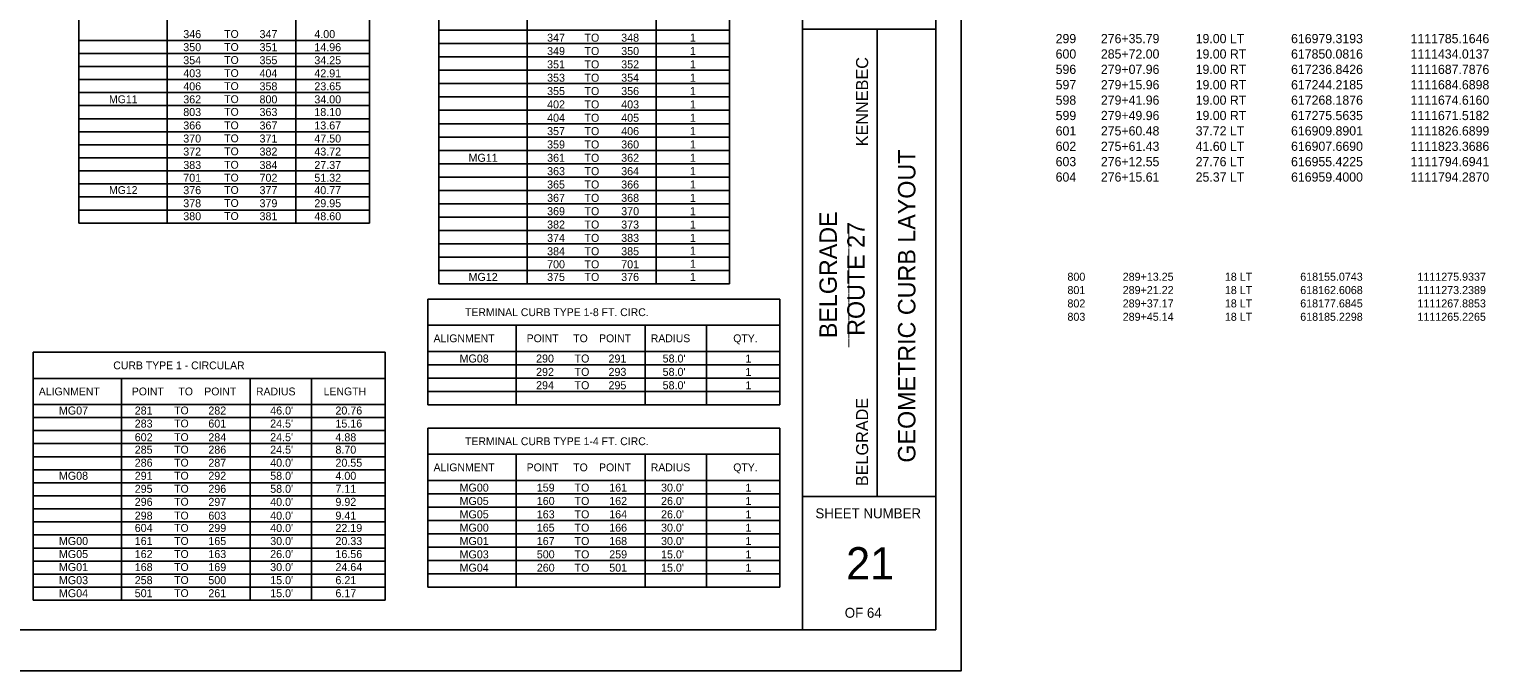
# Model space of a CAD drawing. Extents: x -415 to 632, y -278 to 272.
# Drawn here: x 85 to 632, y -278 to -37 of the extents above; entities that cross this region are included whole.
import ezdxf

# ---------------------------------------------------------------- set-up
doc = ezdxf.new("R2010")
doc.units = 0
for name, color, linetype in [('ANNOTATION', 7, 'Continuous'), ('BORDER', 7, 'Continuous'), ('BRIDGE_TITLE', 7, 'Continuous'), ('H_V CONTROLS', 7, 'Continuous'), ('HIGHWAY_TITLE', 7, 'Continuous'), ('PLOT BOUNDARY', 7, 'Continuous')]:
    doc.layers.add(name, color=color, linetype=linetype)

msp = doc.modelspace()

# ---------------------------------------------------------------- linework, layer by layer
at = {"layer": 'BORDER'}
for p, q in [((375, -262.5), (375, 262.5)), ((425, -262.49), (425, 262.51)), ((375, -37.49), (425, -37.49)), ((402.96, -212.49), (402.96, -37.49)), ((375, -212.49), (425, -212.49)), ((-375, -262.5), (425, -262.5))]:
    msp.add_line(p, q, dxfattribs=at)
at = {"layer": 'H_V CONTROLS'}
for p, q in [((103.65, 246.69), (103.65, -110.1)), ((212.69, 246.69), (212.69, -110.1)), ((238.63, 246.69), (238.63, -132.86)), ((347.68, 246.69), (347.68, -132.86)), ((136.79, 236.92), (136.79, -110.1)), ((185.09, 236.92), (185.09, -110.1)), ((271.78, 236.92), (271.78, -132.86)), ((320.08, 236.92), (320.08, -132.86)), ((238.63, -37.86), (347.68, -37.86)), ((103.65, -41.67), (212.69, -41.67)), ((238.63, -42.86), (347.68, -42.86)), ((103.65, -46.56), (212.69, -46.56)), ((238.63, -47.86), (347.68, -47.86)), ((103.65, -51.45), (212.69, -51.45)), ((238.63, -52.86), (347.68, -52.86)), ((103.65, -56.33), (212.69, -56.33)), ((238.63, -57.86), (347.68, -57.86)), ((103.65, -61.22), (212.69, -61.22)), ((238.63, -62.86), (347.68, -62.86)), ((238.63, -62.86), (347.68, -62.86)), ((103.65, -66.11), (212.69, -66.11)), ((103.65, -71), (212.69, -71)), ((238.63, -67.86), (347.68, -67.86)), ((103.65, -75.88), (212.69, -75.88)), ((238.63, -72.86), (347.68, -72.86)), ((103.65, -80.77), (212.69, -80.77)), ((238.63, -77.86), (347.68, -77.86)), ((103.65, -85.66), (212.69, -85.66)), ((238.63, -82.86), (347.68, -82.86)), ((103.65, -90.55), (212.69, -90.55)), ((238.63, -87.86), (347.68, -87.86)), ((238.63, -92.86), (347.68, -92.86)), ((103.65, -95.43), (212.69, -95.43)), ((238.63, -97.86), (347.68, -97.86)), ((103.65, -100.32), (212.69, -100.32)), ((238.63, -102.86), (347.68, -102.86)), ((103.65, -105.21), (212.69, -105.21)), ((238.63, -107.86), (347.68, -107.86)), ((103.65, -110.1), (212.69, -110.1)), ((103.65, -110.1), (212.69, -110.1)), ((238.63, -112.86), (347.68, -112.86)), ((238.63, -117.86), (347.68, -117.86)), ((238.63, -122.86), (347.68, -122.86)), ((238.63, -122.86), (347.68, -122.86)), ((238.63, -127.86), (347.68, -127.86)), ((238.63, -132.86), (347.68, -132.86)), ((238.63, -132.86), (347.68, -132.86)), ((234.51, -138.59), (366.55, -138.59)), ((234.51, -138.59), (234.51, -178.14)), ((234.51, -138.59), (234.51, -178.14)), ((366.55, -138.59), (366.55, -178.14)), ((234.51, -148.36), (366.55, -148.36)), ((267.65, -148.36), (267.65, -178.14)), ((267.65, -148.36), (267.65, -178.14)), ((315.95, -148.36), (315.95, -178.14)), ((315.95, -148.36), (315.95, -178.14)), ((338.95, -148.36), (338.95, -178.14)), ((86.5, -158.51), (218.54, -158.51)), ((86.5, -158.51), (86.5, -251.37)), ((218.54, -158.51), (218.54, -251.37)), ((234.51, -158.14), (366.55, -158.14)), ((234.51, -158.14), (343.55, -158.14)), ((234.51, -163.14), (366.55, -163.14)), ((86.5, -168.28), (218.54, -168.28)), ((119.64, -168.28), (119.64, -251.37)), ((167.94, -168.28), (167.94, -251.37)), ((190.94, -168.28), (190.94, -251.37)), ((234.51, -168.14), (366.55, -168.14)), ((234.51, -173.14), (366.55, -173.14)), ((86.5, -178.06), (218.54, -178.06)), ((234.51, -178.14), (366.55, -178.14)), ((234.51, -178.14), (366.55, -178.14)), ((86.5, -182.94), (218.54, -182.94)), ((86.5, -187.83), (218.54, -187.83)), ((234.51, -186.93), (366.55, -186.93)), ((234.51, -186.93), (234.51, -246.48)), ((234.51, -186.93), (234.51, -246.48)), ((366.55, -186.93), (366.55, -246.48)), ((86.5, -192.72), (218.54, -192.72)), ((234.51, -196.71), (366.55, -196.71)), ((267.65, -196.71), (267.65, -246.48)), ((267.65, -196.71), (267.65, -246.48)), ((315.95, -196.71), (315.95, -246.48)), ((315.95, -196.71), (315.95, -246.48)), ((338.95, -196.71), (338.95, -246.48)), ((86.5, -197.61), (218.54, -197.61)), ((86.5, -202.49), (218.54, -202.49)), ((86.5, -207.38), (218.54, -207.38)), ((234.51, -206.48), (366.55, -206.48)), ((234.51, -206.48), (343.55, -206.48)), ((86.5, -212.27), (218.54, -212.27)), ((234.51, -211.48), (366.55, -211.48)), ((86.5, -217.16), (218.54, -217.16)), ((234.51, -216.48), (366.55, -216.48)), ((86.5, -222.04), (218.54, -222.04)), ((234.51, -221.48), (366.55, -221.48)), ((86.5, -226.93), (218.54, -226.93)), ((234.51, -226.48), (366.55, -226.48)), ((86.5, -231.82), (218.54, -231.82)), ((234.51, -231.48), (366.55, -231.48)), ((86.5, -236.71), (218.54, -236.71)), ((234.51, -236.48), (366.55, -236.48)), ((86.5, -241.59), (218.54, -241.59)), ((234.51, -241.48), (366.55, -241.48)), ((86.5, -246.48), (218.54, -246.48)), ((86.5, -251.37), (218.54, -251.37)), ((234.51, -246.48), (366.55, -246.48)), ((234.51, -246.48), (366.55, -246.48))]:
    msp.add_line(p, q, dxfattribs=at)
at = {"layer": 'PLOT BOUNDARY'}
msp.add_lwpolyline([(-415.47, -277.8), (434.53, -277.8), (434.53, 272.2), (-415.47, 272.2)], close=True, dxfattribs=at)

# ---------------------------------------------------------------- texts
at = {"layer": 'ANNOTATION'}
for s, height, p in [('346', 3, (142.83, -40.81)), ('347', 3, (171.42, -40.81)), ('4.00', 3, (191.97, -40.81)), ('350', 3, (142.83, -45.7)), ('351', 3, (171.42, -45.7)), ('14.96', 3, (191.97, -45.7)), ('347', 3, (279.24, -42.14)), ('TO', 3, (293.24, -42.14)), ('348', 3, (307.02, -42.14)), ('1', 3, (332.76, -42.14)), ('299', 3.45, (469.9, -42.71)), ('276+35.79', 3.45, (486.86, -42.71)), ('19.00 LT', 3.45, (522.4, -42.71)), ('616979.3193', 3.45, (558.16, -42.71)), ('1111785.1646', 3.45, (602.97, -42.71)), ('354', 3, (142.83, -50.59)), ('355', 3, (171.42, -50.59)), ('34.25', 3, (191.97, -50.59)), ('349', 3, (279.24, -47.14)), ('351', 3, (279.24, -52.14)), ('TO', 3, (293.24, -47.14)), ('TO', 3, (293.24, -52.14)), ('350', 3, (307.02, -47.14)), ('352', 3, (307.02, -52.14)), ('1', 3, (332.76, -47.14)), ('1', 3, (332.76, -52.14)), ('600', 3.45, (469.9, -48.47)), ('285+72.00', 3.45, (486.86, -48.47)), ('19.00 RT', 3.45, (522.4, -48.47)), ('617850.0816', 3.45, (558.16, -48.47)), ('1111434.0137', 3.45, (602.97, -48.47)), ('403', 3, (142.83, -55.48)), ('404', 3, (171.42, -55.48)), ('42.91', 3, (191.97, -55.48)), ('353', 3, (279.24, -57.14)), ('TO', 3, (293.24, -57.14)), ('354', 3, (307.02, -57.14)), ('1', 3, (332.76, -57.14)), ('596', 3.45, (469.9, -54.23)), ('279+07.96', 3.45, (486.86, -54.23)), ('19.00 RT', 3.45, (522.4, -54.23)), ('617236.8426', 3.45, (558.16, -54.23)), ('1111687.7876', 3.45, (602.97, -54.23)), ('406', 3, (142.83, -60.36)), ('358', 3, (171.42, -60.36)), ('23.65', 3, (191.97, -60.36)), ('355', 3, (279.24, -62.14)), ('TO', 3, (293.24, -62.14)), ('356', 3, (307.02, -62.14)), ('1', 3, (332.76, -62.14)), ('597', 3.45, (469.9, -60)), ('279+15.96', 3.45, (486.86, -60)), ('19.00 RT', 3.45, (522.4, -60)), ('617244.2185', 3.45, (558.16, -60)), ('1111684.6898', 3.45, (602.97, -60)), ('362', 3, (142.83, -65.25)), ('800', 3, (171.42, -65.25)), ('34.00', 3, (191.97, -65.25)), ('402', 3, (279.24, -67.14)), ('TO', 3, (293.24, -67.14)), ('403', 3, (307.02, -67.14)), ('1', 3, (332.76, -67.14)), ('598', 3.45, (469.9, -65.76)), ('279+41.96', 3.45, (486.86, -65.76)), ('19.00 RT', 3.45, (522.4, -65.76)), ('617268.1876', 3.45, (558.16, -65.76)), ('1111674.6160', 3.45, (602.97, -65.76)), ('803', 3, (142.83, -70)), ('363', 3, (171.42, -70)), ('18.10', 3, (191.97, -70)), ('404', 3, (279.24, -72.14)), ('TO', 3, (293.24, -72.14)), ('405', 3, (307.02, -72.14)), ('1', 3, (332.76, -72.14)), ('599', 3.45, (469.9, -71.52)), ('279+49.96', 3.45, (486.86, -71.52)), ('19.00 RT', 3.45, (522.4, -71.52)), ('617275.5635', 3.45, (558.16, -71.52)), ('1111671.5182', 3.45, (602.97, -71.52)), ('366', 3, (142.83, -75.03)), ('367', 3, (171.42, -75.03)), ('13.67', 3, (191.97, -75.03)), ('357', 3, (279.24, -77.14)), ('TO', 3, (293.24, -77.14)), ('406', 3, (307.02, -77.14)), ('1', 3, (332.76, -77.14)), ('601', 3.45, (469.9, -77.28)), ('275+60.48', 3.45, (486.86, -77.28)), ('37.72 LT', 3.45, (522.4, -77.28)), ('616909.8901', 3.45, (558.16, -77.28)), ('1111826.6899', 3.45, (602.97, -77.28)), ('370', 3, (142.83, -79.92)), ('372', 3, (142.83, -84.8)), ('371', 3, (171.42, -79.92)), ('382', 3, (171.42, -84.8)), ('47.50', 3, (191.97, -79.92)), ('43.72', 3, (191.97, -84.8)), ('359', 3, (279.24, -82.14)), ('TO', 3, (293.24, -82.14)), ('360', 3, (307.02, -82.14)), ('1', 3, (332.76, -82.14)), ('602', 3.45, (469.9, -83.04)), ('275+61.43', 3.45, (486.86, -83.04)), ('41.60 LT', 3.45, (522.4, -83.04)), ('616907.6690', 3.45, (558.16, -83.04)), ('1111823.3686', 3.45, (602.97, -83.04)), ('383', 3, (142.83, -89.83)), ('384', 3, (171.42, -89.83)), ('27.37', 3, (191.97, -89.83)), ('MG11', 3, (249.79, -87.14)), ('361', 3, (279.24, -87.14)), ('TO', 3, (293.24, -87.14)), ('362', 3, (307.02, -87.14)), ('1', 3, (332.76, -87.14)), ('603', 3.45, (469.9, -88.8)), ('276+12.55', 3.45, (486.86, -88.8)), ('27.76 LT', 3.45, (522.4, -88.8)), ('616955.4225', 3.45, (558.16, -88.8)), ('1111794.6941', 3.45, (602.97, -88.8)), ('701', 3, (142.83, -94.62)), ('702', 3, (171.42, -94.62)), ('51.32', 3, (191.97, -94.62)), ('363', 3, (279.24, -92.14)), ('TO', 3, (293.24, -92.14)), ('364', 3, (307.02, -92.14)), ('1', 3, (332.76, -92.14)), ('604', 3.45, (469.9, -94.57)), ('276+15.61', 3.45, (486.86, -94.57)), ('25.37 LT', 3.45, (522.4, -94.57)), ('616959.4000', 3.45, (558.16, -94.57)), ('1111794.2870', 3.45, (602.97, -94.57)), ('376', 3, (142.83, -99.26)), ('377', 3, (171.42, -99.26)), ('40.77', 3, (191.97, -99.26)), ('365', 3, (279.24, -97.14)), ('TO', 3, (293.24, -97.14)), ('366', 3, (307.02, -97.14)), ('1', 3, (332.76, -97.14)), ('378', 3, (142.83, -104.15)), ('379', 3, (171.42, -104.15)), ('29.95', 3, (191.97, -104.15)), ('367', 3, (279.24, -102.14)), ('TO', 3, (293.24, -102.14)), ('368', 3, (307.02, -102.14)), ('1', 3, (332.76, -102.14)), ('380', 3, (142.83, -109.04)), ('381', 3, (171.42, -109.04)), ('48.60', 3, (191.97, -109.04)), ('369', 3, (279.24, -107.14)), ('382', 3, (279.24, -112.14)), ('TO', 3, (293.24, -107.14)), ('TO', 3, (293.24, -112.14)), ('370', 3, (307.02, -107.14)), ('373', 3, (307.02, -112.14)), ('1', 3, (332.76, -107.14)), ('1', 3, (332.76, -112.14)), ('374', 3, (279.24, -117.14)), ('TO', 3, (293.24, -117.14)), ('383', 3, (307.02, -117.14)), ('1', 3, (332.76, -117.14)), ('384', 3, (279.24, -122.14)), ('TO', 3, (293.24, -122.14)), ('385', 3, (307.02, -122.14)), ('1', 3, (332.76, -121.95)), ('700', 3, (279.24, -127.03)), ('TO', 3, (293.24, -127.03)), ('701', 3, (307.02, -127.03)), ('1', 3, (332.76, -126.85)), ('MG12', 3, (249.79, -131.77)), ('375', 3, (279.24, -131.77)), ('TO', 3, (293.24, -131.77)), ('376', 3, (307.02, -131.77)), ('1', 3, (332.76, -131.77)), ('800', 3, (474.32, -131.69)), ('289+13.25', 3, (495.04, -131.69)), ('18 LT', 3, (533.34, -131.69)), ('618155.0743', 3, (561.6, -131.69)), ('1111275.9337', 3, (605.55, -131.69)), ('801', 3, (474.32, -136.69)), ('289+21.22', 3, (495.04, -136.69)), ('18 LT', 3, (533.34, -136.69)), ('618162.6068', 3, (561.6, -136.69)), ('1111273.2389', 3, (605.55, -136.69)), ('802', 3, (474.32, -141.69)), ('289+37.17', 3, (495.04, -141.69)), ('18 LT', 3, (533.34, -141.69)), ('618177.6845', 3, (561.6, -141.69)), ('1111267.8853', 3, (605.55, -141.69)), ('803', 3, (474.32, -146.69)), ('289+45.14', 3, (495.04, -146.69)), ('18 LT', 3, (533.34, -146.69)), ('618185.2298', 3, (561.6, -146.69)), ('1111265.2265', 3, (605.55, -146.69)), ('MG08', 3, (246.42, -162.33)), ('290', 3, (275.11, -162.33)), ('TO', 3, (289.52, -162.33)), ('291', 3, (302.26, -162.33)), ("58.0'", 3, (322.55, -162.33)), ('1', 3, (353.6, -162.33)), ('292', 3, (275.11, -167.33)), ('294', 3, (275.11, -172.33)), ('TO', 3, (289.52, -167.33)), ('TO', 3, (289.52, -172.33)), ('293', 3, (302.26, -167.33)), ('295', 3, (302.26, -172.33)), ("58.0'", 3, (322.55, -167.33)), ("58.0'", 3, (322.55, -172.33)), ('1', 3, (353.6, -167.33)), ('1', 3, (353.6, -172.33)), ('MG07', 3, (96.21, -181.81)), ('281', 3, (124.63, -181.81)), ('282', 3, (152.23, -181.81)), ("46.0'", 3, (175.42, -181.81)), ('20.76', 3, (199.88, -181.81)), ('283', 3, (124.63, -186.69)), ('601', 3, (152.23, -186.69)), ("24.5'", 3, (175.42, -186.69)), ('15.16', 3, (199.88, -186.69)), ('602', 3, (124.63, -191.81)), ('284', 3, (152.23, -191.81)), ("24.5'", 3, (175.42, -191.81)), ('4.88', 3, (199.88, -191.81)), ('285', 3, (124.63, -196.47)), ('286', 3, (152.23, -196.47)), ("24.5'", 3, (175.42, -196.47)), ('8.70', 3, (199.88, -196.47)), ('286', 3, (124.63, -201.36)), ('287', 3, (152.23, -201.36)), ("40.0'", 3, (175.42, -201.36)), ('20.55', 3, (199.88, -201.36)), ('MG08', 3, (96.21, -206.25)), ('291', 3, (124.63, -206.25)), ('292', 3, (152.23, -206.25)), ("58.0'", 3, (175.42, -206.25)), ('4.00', 3, (199.88, -206.25)), ('MG00', 3, (246.42, -210.68)), ('159', 3, (275.37, -210.68)), ('TO', 3, (289.52, -210.68)), ('161', 3, (302.53, -210.68)), ("30.0'", 3, (321.96, -210.68)), ('1', 3, (353.6, -210.68)), ('295', 3, (124.63, -211.13)), ('296', 3, (124.63, -216.02)), ('296', 3, (152.23, -211.13)), ('297', 3, (152.23, -216.02)), ("40.0'", 3, (175.42, -216.02)), ("58.0'", 3, (175.42, -211.13)), ('9.92', 3, (199.88, -216.02)), ('7.11', 3, (199.88, -211.13)), ('MG05', 3, (246.42, -215.68)), ('160', 3, (275.37, -215.68)), ('TO', 3, (289.52, -215.68)), ('162', 3, (302.53, -215.68)), ("26.0'", 3, (321.96, -215.68)), ('1', 3, (353.6, -215.68)), ('298', 3, (124.63, -221.18)), ('603', 3, (152.23, -221.18)), ("40.0'", 3, (175.42, -221.18)), ('9.41', 3, (199.88, -221.18)), ('MG05', 3, (246.42, -220.68)), ('163', 3, (275.37, -220.68)), ('TO', 3, (289.52, -220.68)), ('164', 3, (302.53, -220.68)), ("26.0'", 3, (321.96, -220.68)), ('1', 3, (353.6, -220.68)), ('604', 3, (124.63, -225.8)), ('299', 3, (152.23, -225.8)), ("40.0'", 3, (175.42, -225.8)), ('22.19', 3, (199.88, -225.8)), ('MG00', 3, (246.42, -225.68)), ('165', 3, (275.37, -225.68)), ('TO ', 3, (289.52, -225.68)), ('166', 3, (302.53, -225.68)), ("30.0'", 3, (321.96, -225.68)), ('1', 3, (353.6, -225.68)), ('MG00', 3, (96.21, -230.69)), ('161', 3, (124.63, -230.69)), ('165', 3, (152.23, -230.69)), ("30.0'", 3, (175.42, -230.69)), ('20.33', 3, (199.88, -230.69)), ('MG01', 3, (246.42, -230.68)), ('167', 3, (275.37, -230.68)), ('TO', 3, (289.52, -230.68)), ('168', 3, (302.53, -230.68)), ("30.0'", 3, (321.96, -230.68)), ('1', 3, (353.6, -230.68)), ('MG05', 3, (96.21, -235.57)), ('162', 3, (124.63, -235.57)), ('163', 3, (152.23, -235.57)), ("26.0'", 3, (175.42, -235.57)), ('16.56', 3, (199.88, -235.57)), ('MG03', 3, (246.42, -235.68)), ('500', 3, (275.37, -235.68)), ('TO', 3, (289.52, -235.68)), ('259', 3, (302.53, -235.68)), ("15.0'", 3, (321.96, -235.68)), ('1', 3, (353.6, -235.68)), ('MG01', 3, (96.21, -240.46)), ('168', 3, (124.63, -240.46)), ('169', 3, (152.23, -240.46)), ("30.0'", 3, (175.42, -240.46)), ('24.64', 3, (199.88, -240.46)), ('MG04', 3, (246.42, -240.68)), ('260', 3, (275.37, -240.68)), ('TO', 3, (289.52, -240.68)), ('501', 3, (302.53, -240.68)), ("15.0'", 3, (321.96, -240.68)), ('1', 3, (353.6, -240.68)), ('MG03', 3, (96.21, -245.35)), ('258', 3, (124.63, -245.35)), ('500', 3, (152.23, -245.35)), ("15.0'", 3, (175.42, -245.35)), ('6.21', 3, (199.88, -245.35)), ('MG04', 3, (96.21, -250.24)), ('501', 3, (124.63, -250.24)), ('261', 3, (152.23, -250.24)), ("15.0'", 3, (175.42, -250.24)), ('6.17', 3, (199.88, -250.24))]:
    msp.add_text(s, height=height, dxfattribs=at).set_placement(p)
for s, height, p in [('TO', 2.932, (158.17, -40.71)), ('TO', 2.932, (158.17, -45.6)), ('TO', 2.932, (158.17, -50.49)), ('TO', 2.932, (158.17, -55.38)), ('TO', 2.932, (158.17, -60.26)), ('MG11', 2.932, (114.99, -65.18)), ('TO', 2.932, (158.17, -65.15)), ('TO', 2.932, (158.17, -69.9)), ('TO', 2.932, (158.17, -74.93)), ('TO', 2.932, (158.17, -79.82)), ('TO', 2.932, (158.17, -84.7)), ('TO', 2.932, (158.17, -89.73)), ('TO', 2.932, (158.17, -94.52)), ('MG12', 2.932, (114.99, -99.19)), ('TO', 2.932, (158.17, -99.16)), ('TO', 2.932, (158.17, -104.05)), ('TO', 2.932, (158.17, -108.93)), ('TO', 2.933, (139.41, -181.74)), ('TO', 2.933, (139.41, -186.63)), ('TO', 2.933, (139.41, -191.74)), ('TO', 2.933, (139.41, -196.4)), ('TO', 2.933, (139.41, -201.29)), ('TO', 2.933, (139.41, -206.18)), ('TO', 2.933, (139.41, -211.07)), ('TO', 2.933, (139.41, -215.95)), ('TO', 2.933, (139.41, -221.11)), ('TO', 2.933, (139.41, -225.73)), ('TO', 2.933, (139.41, -230.62)), ('TO', 2.933, (139.41, -235.51)), ('TO', 2.933, (139.41, -240.39)), ('TO', 2.933, (139.41, -245.28)), ('TO', 2.933, (139.41, -250.17))]:
    msp.add_text(s, height=height, rotation=360, dxfattribs=at).set_placement(p)
at = {"layer": 'BORDER'}
msp.add_text('GEOMETRIC CURB LAYOUT', height=6.5214, rotation=90, dxfattribs=at).set_placement((417.32, -199.81))
for s, height, p in [('SHEET NUMBER', 3.7264, (379.83, -220.67)), ('21', 12.097, (391.36, -243.59)), ('OF 64', 3.726, (390.83, -257.94))]:
    msp.add_text(s, height=height, dxfattribs=at).set_placement(p)
at = {"layer": 'BRIDGE_TITLE'}
for s, height, p in [('KENNEBEC', 4.536, (399.6, -81.29)), ('_____________', 4.5358, (391.22, -156.54)), ('BELGRADE', 4.536, (399.6, -208.62))]:
    msp.add_text(s, height=height, rotation=90, dxfattribs=at).set_placement(p)
at = {"layer": 'H_V CONTROLS'}
for s, height, p in [('TERMINAL CURB TYPE 1-8 FT. CIRC.', 2.9325, (248.47, -144.94)), ('ALIGNMENT', 2.932, (236.68, -154.72)), ('ALIGNMENT', 2.932, (236.68, -154.72)), ('POINT', 2.932, (271.57, -154.72)), ('POINT', 2.932, (271.57, -154.72)), ('TO', 2.932, (289.03, -154.72)), ('TO', 2.932, (289.03, -154.72)), ('POINT', 2.932, (298.72, -154.72)), ('POINT', 2.932, (298.72, -154.72)), ('RADIUS', 2.932, (318.1, -154.72)), ('QTY.', 2.932, (349.03, -154.72)), ('CURB TYPE 1 - CIRCULAR', 2.9325, (116.58, -164.86)), ('ALIGNMENT', 2.932, (88.67, -174.63)), ('POINT', 2.932, (123.55, -174.63)), ('TO', 2.932, (141.02, -174.63)), ('POINT', 2.932, (150.71, -174.63)), ('RADIUS', 2.932, (170.09, -174.63)), ('LENGTH', 2.932, (195.46, -174.63)), ('TERMINAL CURB TYPE 1-4 FT. CIRC.', 2.9325, (248.47, -193.28)), ('ALIGNMENT', 2.932, (236.68, -203.06)), ('ALIGNMENT', 2.932, (236.68, -203.06)), ('POINT', 2.932, (271.57, -203.06)), ('POINT', 2.932, (271.57, -203.06)), ('TO', 2.932, (289.03, -203.06)), ('TO', 2.932, (289.03, -203.06)), ('POINT', 2.932, (298.72, -203.06)), ('POINT', 2.932, (298.72, -203.06)), ('RADIUS', 2.932, (318.1, -203.06)), ('QTY.', 2.932, (349.03, -203.06))]:
    msp.add_text(s, height=height, rotation=360, dxfattribs=at).set_placement(p)
at = {"layer": 'HIGHWAY_TITLE'}
for s, p in [('BELGRADE', (387.86, -153.21)), ('ROUTE 27', (398.3, -152.33))]:
    msp.add_text(s, height=6.521, rotation=90, dxfattribs=at).set_placement(p)

doc.saveas('drawing.dxf')
